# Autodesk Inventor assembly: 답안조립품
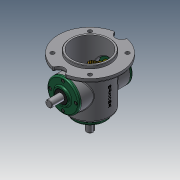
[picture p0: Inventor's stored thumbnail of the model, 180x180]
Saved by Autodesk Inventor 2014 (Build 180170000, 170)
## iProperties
Created: 2018-04
Part Number: 답안조립품
Document SubType Name: Assembly
Designer: NET
Author: NET
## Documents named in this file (16)
- C:\Users\NET\Desktop\480407V1003\답안조립품.iam
- C:\Users\NET\Desktop\480407V1003\본체.ipt
- C:\Users\NET\Desktop\480407V1003\메인 축.ipt
- 메인 축.ipt
- C:\Users\NET\Desktop\480407V1003\베어링 6203.ipt
- C:\Users\NET\Desktop\480407V1003\커버.ipt
- C:\Users\NET\Desktop\480407V1003\오일 실.ipt
- 오일 실.ipt
- C:\Users\NET\Desktop\480407V1003\메인 베벨기어.ipt
- C:\Users\NET\Desktop\480407V1003\키 5x5.ipt
- C:\Users\NET\Desktop\480407V1003\볼트 M4.ipt
- 볼트 M4.ipt
- C:\Users\NET\Desktop\480407V1003\서브 축.ipt
- 서브 축.ipt
- C:\Users\NET\Desktop\480407V1003\서브 베벨기어.ipt
- C:\Users\NET\Desktop\480407V1003\키 4x4.ipt
